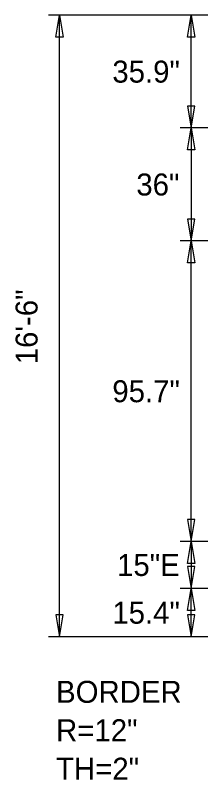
# Model space of a CAD drawing. Extents: x 2149961 to 2150220, y 145114 to 145240.
# Drawn here: x 2150189.58 to 2150194.7, y 145152.79 to 145173.09 of the extents above; entities that cross this region are included whole.
import ezdxf

# ---------------------------------------------------------------- set-up
doc = ezdxf.new("R2010")
doc.units = 0
doc.layers.add('GSDIMS', color=7, linetype='Continuous')

msp = doc.modelspace()

# ---------------------------------------------------------------- linework, layer by layer
at = {"layer": 'GSDIMS'}
for p, q in [((2150191.196, 145173.085), (2150190.467, 145173.085)), ((2150190.759, 145156.585), (2150190.759, 145173.085)), ((2150194.696, 145173.085), (2150191.196, 145173.085)), ((2150194.696, 145173.085), (2150193.967, 145173.085)), ((2150194.259, 145170.094), (2150194.259, 145173.085)), ((2150194.696, 145170.094), (2150193.967, 145170.094)), ((2150194.696, 145170.094), (2150193.967, 145170.094)), ((2150194.259, 145170.094), (2150194.259, 145167.094)), ((2150194.696, 145167.094), (2150193.967, 145167.094)), ((2150194.696, 145167.094), (2150193.967, 145167.094)), ((2150194.259, 145159.119), (2150194.259, 145167.094)), ((2150194.696, 145159.119), (2150193.967, 145159.119)), ((2150194.696, 145159.119), (2150193.967, 145159.119)), ((2150194.259, 145159.119), (2150194.259, 145157.869)), ((2150194.696, 145157.869), (2150193.967, 145157.869)), ((2150194.696, 145157.869), (2150193.967, 145157.869)), ((2150194.259, 145156.585), (2150194.259, 145157.869)), ((2150191.196, 145156.585), (2150190.467, 145156.585)), ((2150194.696, 145156.585), (2150191.196, 145156.585)), ((2150194.696, 145156.585), (2150193.967, 145156.585))]:
    msp.add_line(p, q, dxfattribs=at)
for points in [[(2150190.759, 145173.085), (2150190.856, 145172.502), (2150190.661, 145172.502)], [(2150194.259, 145173.085), (2150194.356, 145172.502), (2150194.161, 145172.502)], [(2150194.259, 145170.094), (2150194.356, 145170.677), (2150194.161, 145170.677)], [(2150194.259, 145170.094), (2150194.356, 145169.51), (2150194.161, 145169.51)], [(2150194.259, 145167.094), (2150194.356, 145167.677), (2150194.161, 145167.677)], [(2150194.259, 145167.094), (2150194.356, 145166.51), (2150194.161, 145166.51)], [(2150194.259, 145159.119), (2150194.356, 145159.702), (2150194.161, 145159.702)], [(2150194.259, 145159.119), (2150194.356, 145158.535), (2150194.161, 145158.535)], [(2150194.259, 145157.869), (2150194.356, 145158.452), (2150194.161, 145158.452)], [(2150194.259, 145157.869), (2150194.356, 145157.285), (2150194.161, 145157.285)], [(2150190.759, 145156.585), (2150190.856, 145157.169), (2150190.661, 145157.169)], [(2150194.259, 145156.585), (2150194.356, 145157.169), (2150194.161, 145157.169)]]:
    msp.add_lwpolyline(points, close=True, dxfattribs=at)

# ---------------------------------------------------------------- texts
for s, p in [('35.9"', (2150192.162, 145171.298)), ('36"', (2150192.799, 145168.302)), ('95.7"', (2150192.162, 145162.814)), ('15"E', (2150192.288, 145158.202)), ('15.4"', (2150192.162, 145156.935)), ('BORDER', (2150190.667, 145154.835)), ('R=12"', (2150190.667, 145153.815)), ('TH=2"', (2150190.667, 145152.794))]:
    msp.add_text(s, height=0.5833, dxfattribs=at).set_placement(p)
msp.add_text('16\'-6"', height=0.5833, rotation=90, dxfattribs=at).set_placement((2150190.175, 145163.821))

doc.saveas('drawing.dxf')
